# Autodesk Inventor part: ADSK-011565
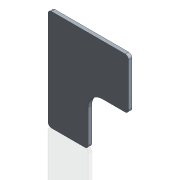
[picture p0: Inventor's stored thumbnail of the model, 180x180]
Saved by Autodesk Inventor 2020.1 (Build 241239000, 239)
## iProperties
Created: 2000-02
Part Number: ADSK-011565
Material: Pearson Aluminium
Document SubType Name: Modeling
Designer: cmcgourin
Density: 2.71 g/cm^3
Appearance: Pearson-Aluminum
Mass: 2457.99 g
Surface Area: 1666.55 cm^2
Volume: 907.008 cm^3
Control State: 0
Checked Out: False
Master: False
Shininess: 0.0
Length Units: 11269
Angle Units: 11279
Time Units: 11290
Mass Units: 11283
Length Display Precision: 3
Angle Display Precision: 2
Compacted: True
Dimensions: 283x355x12 mm
Mass: 2,458 kg
Density: 0.0
Volumn: 0.0
Area: 0.0
PropertySet Name: Model Information
Author: cmcgourin
Revision Number: -
Title: ADSK-011565
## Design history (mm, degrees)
sketch "Skizze3"
  geometry: L1 (-45.75, -169.75)-(-95.75, -169.75); L2 (-95.75, -169.75)-(-95.75, -147.25); L3 (-95.75, -147.25)-(-45.75, -147.25); L4 (-45.75, -147.25)-(-45.75, -169.75); L5 (-12, -177.5)-(-129.5, -177.5) reference; 7 further points
  constraints: 8 end point, 4 coincident, 2 midpoint, 2 parallel, 1 horizontal, 1 perpendicular, 1 vertical alignment
  dimensions: "d12" = 50 distance of L1.start L1.end; "d13" = 22.5 distance of L1.end L2.end; "d14" = 7.75 distance between parallel lines of L5 L1
hole "Bohrung1" sketch "Skizze3" at (-45.75, -169.75), (-95.75, -169.75), (-95.75, -147.25), (-45.75, -147.25) diameter "d15" = 4.917; stored, may be unused: countersink angle "d19" = 90 deg, drill point angle "d21" = 118 deg; dims "d16" = 12, "d17" = 4, "d18" = 2, "d20" = 17.1
workplane "Arbeitsebene1"
node "Solide1"
  node "Extrusion1" dims "d2" = 12, "d3" = 0
  node "Extrusion2" dims "d5" = 12.7, "d6" = 0
  node "Fillet1" dims "d7" = 50
  node "Fillet2" dims "d8" = 12
sketch "Sketch1"
  geometry: L1 (-141.5, -177.5)-(141.5, -177.5); L2 (141.5, -177.5)-(141.5, 177.5); L3 (141.5, 177.5)-(-141.5, 177.5); L4 (-141.5, 177.5)-(-141.5, -177.5); 3 further points
  constraints: 8 end point, 2 midpoint, 2 parallel, 1 horizontal, 1 horizontal alignment, 1 perpendicular, 1 vertical alignment
  dimensions: "d0" = 355 distance of L3.end L1.start; "d9" = 283 distance of L2.end L3.end
sketch "Sketch2"
  geometry: L1 (141.5, 177.5)-(141.5, -177.5) reference; L2 (0, -177.5)-(141.5, -177.5); L3 (141.5, -177.5)-(141.5, 0.5); L4 (141.5, 0.5)-(0, 0.5); L5 (0, 0.5)-(0, -177.5); L6 (141.5, -177.5)-(-141.5, -177.5) reference; 1 further point
  constraints: 8 end point, 2 parallel, 1 coincident, 1 horizontal, 1 midpoint, 1 perpendicular, 1 point on line
  dimensions: "d11" = 178 distance of L4.end L2.start
node "Corps solides"
node "Corps surfaciques"
